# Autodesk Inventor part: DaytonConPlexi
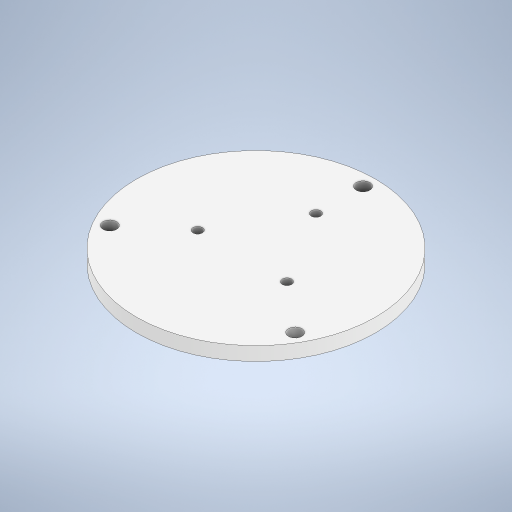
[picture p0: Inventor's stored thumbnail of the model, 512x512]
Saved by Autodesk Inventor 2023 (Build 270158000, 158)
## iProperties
Created: 2023-06
Part Number: DaytonConPlexi
Material: Generic
Document SubType Name: Modeling
Designer: Admin
Density: 1 g/cm^3
Appearance: Default
Author: Admin
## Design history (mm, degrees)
sketch "Sketch1"
  geometry: L1 (19.6, 6)-(0, 6); L2 (0, 6)-(-19.6, 6); C1 r 52.5 at (0, 0); C2 r 3 at (0, -47); C3 r 3 at (40.703, 23.5); C4 r 3 at (-40.703, 23.5); C5 r 2.1 at (19.6, 6); C6 r 2.1 at (0, -26.333); C7 r 2.1 at (-19.6, 6); A1 r 47 centre (0, 0) between (0, -47) and (-40.703, 23.5); 1 further point
  constraints: 8 centre point, 4 end point, 3 vertical alignment, 2 coincident, 2 collinear, 2 equal radius, 2 point on circle, 1 horizontal, 7 other
  dimensions: "d0" = 105 diameter of C1; "d1" = 94 diameter of A1; "d2" = 6 diameter of C2; "d5" = 360 deg dimension on A1.centre C2.centre (derived); "d9" = 19.6 horizontal distance of L1.start point (0, 0); "d10" = 6 vertical distance of point (0, 0) L1.start; "d11" = 4.2 diameter of C5; "d12" = 26.333 distance of C6.centre point (0, 0)
extrude "Extrusion1" new body sketch "Sketch1" distance "d7" = 6; taper "d8" = 0 deg
body "Solid1"
